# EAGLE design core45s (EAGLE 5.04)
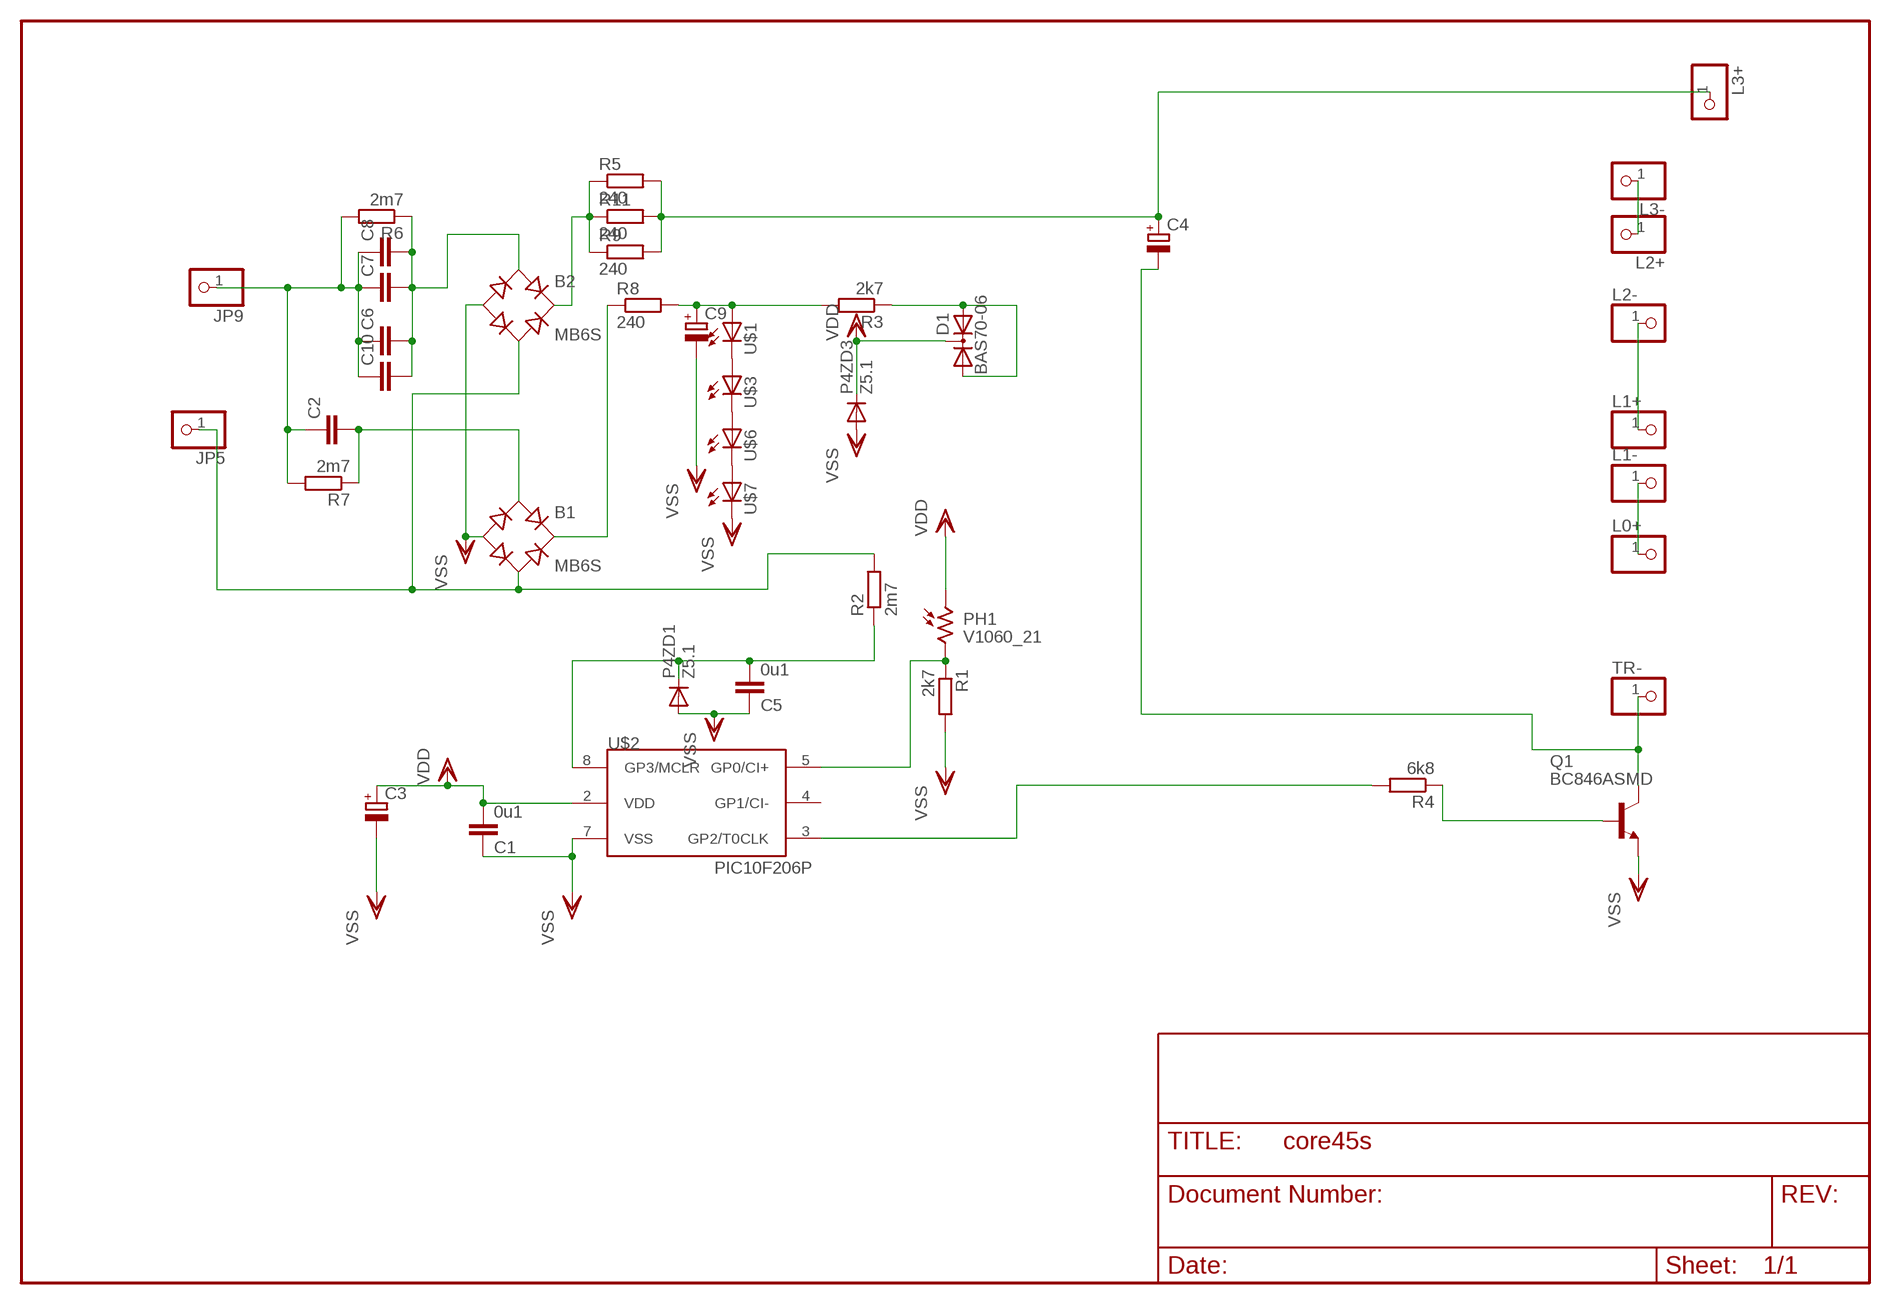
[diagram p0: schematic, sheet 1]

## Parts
B1  MB6S  [SOIC-4]
B2  MB6S  [SOIC-4]
C1  0u1  C-EUC1206  [C1206]
C2  C-EU102-043X133  [C102-043X133]
C3  CPOL-EU5-13  [2,5-5-FLAT]
C4  CPOL-EUTT5D11L  [TT5D11L]
C5  0u1  C-EUC1206  [C1206]
C6  C-EU150-064X183  [C150-064X183]
C7  C-EU150-054X183  [C150-054X183]
C8  C-EU150-054X183  [C150-054X183]
C9  CPOL-EUTT5D11L  [TT5D11L]
C10  C-EU150-064X183  [C150-064X183]
D1  BAS70-06  [SOT23]
JP5  PINHD-1X1  [1X01]
JP9  PINHD-1X1  [1X01]
L0+  PINHD-1X1  [1X01]
L1+  PINHD-1X1  [1X01]
L1-  PINHD-1X1  [1X01]
L2+  PINHD-1X1  [1X01]
L2-  PINHD-1X1  [1X01]
L3+  PINHD-1X1  [1X01]
L3-  PINHD-1X1  [1X01]
P4ZD1  Z5.1  DIODE-MINIMELF  [MINIMELF]
P4ZD3  Z5.1  DIODE-MINIMELF  [MINIMELF]
PH1  V1060_21  [TO-5_V10]
Q1  BC846ASMD  [SOT23]
R1  2k7  R-EU_R0805  [R0805]
R2  2m7  R-EU_R1206  [R1206]
R3  2k7  R-EU_R0805  [R0805]
R4  6k8  R-EU_R0805  [R0805]
R5  240  R-EU_R1206  [R1206]
R6  2m7  R-EU_R1206  [R1206]
R7  2m7  R-EU_R1206  [R1206]
R8  240  R-EU_R1206  [R1206]
R9  240  R-EU_R1206  [R1206]
R11  240  R-EU_R1206  [R1206]
TR-  PINHD-1X1  [1X01]
U$1  LED5MM  [LED5MM]
U$2  PIC10F206P  [DIL8]
U$3  LED5MM  [LED5MM]
U$6  LED5MM  [LED5MM]
U$7  LED5MM  [LED5MM]

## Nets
AC1: B1.~2(AC2) B2.~2(AC2) JP5.1 R2.2
AC2: C2.1 C6.1 C7.1 C8.1 C10.1 JP9.1 R6.2 R7.2
D+: C4.+ L3+.1 R5.2 R9.2 R11.2
LED-: C4.- Q1.3(C) TR-.1
N$1: C5.2 P4ZD1.C R2.1 U$2.8(GP3/MCLR)
N$2: B1.+ R8.1
N$3: L0+.1 L1-.1
N$4: C9.+ R3.2 R8.2 U$1.A
N$5: D1.1(A1) D1.2(A2) R3.1
N$6: L1+.1 L2-.1
N$7: U$1.K(C) U$3.A
N$8: B1.~1(AC1) C2.2 R7.1
N$9: B2.~1(AC1) C6.2 C7.2 C8.2 C10.2 R6.1
N$10: U$3.K(C) U$6.A
N$11: B2.+ R5.1 R9.1 R11.1
N$12: Q1.1(B) R4.1
N$13: L2+.1 L3-.1
N$15: R4.2 U$2.3(GP2/T0CLK)
N$16: U$6.K(C) U$7.A
N$17: PH1.2 R1.1 U$2.5(GP0/CI+)
VDD: C1.2 C3.+ D1.3(C) P4ZD3.C PH1.1 U$2.2(VDD)
VSS: B1.- B2.- C1.1 C3.- C5.1 C9.- P4ZD1.A P4ZD3.A Q1.2(E) R1.2 U$2.7(VSS) U$7.K(C)
Unconnected: U$2.4(GP1/CI-)

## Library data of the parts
B1 B2 = rectifier:MB*S: Bridge Rectifier Source: http://www.fairchildsemi.com/ds/MB/MB6S.pdf
C1 C5 = rcl:C-EU: CAPACITOR, European symbol
C2 C6-C8 C10 = rcl-2:C-EU: CAPACITOR, European symbol
C3 C4 C9 = rcl-2:CPOL-EU: POLARIZED CAPACITOR, European symbol
D1 = diode:BAS70-06: Silicon Schottky Diodes General-purpose diode for high-speed switching
JP5 JP9 L0+ L1+ L1- L2+ L2- L3+ L3- TR- = pinhead(2):PINHD-1X1: PIN HEADER
P4ZD1 P4ZD3 = diode:DIODE-: DIODE
PH1 = photo-elements:?1060*: Sensor Street Light control
Q1 = transistor-npn:BC846*: NPN Transistor
R1-R9 R11 = rcl-2:R-EU_: RESISTOR, European symbol
U$1 U$3 U$6 U$7 = led(3):LED: LED
U$2 = microchip-3:PIC10F2*: uPC nW 0,25/0,5k Program Flash memory Comparator

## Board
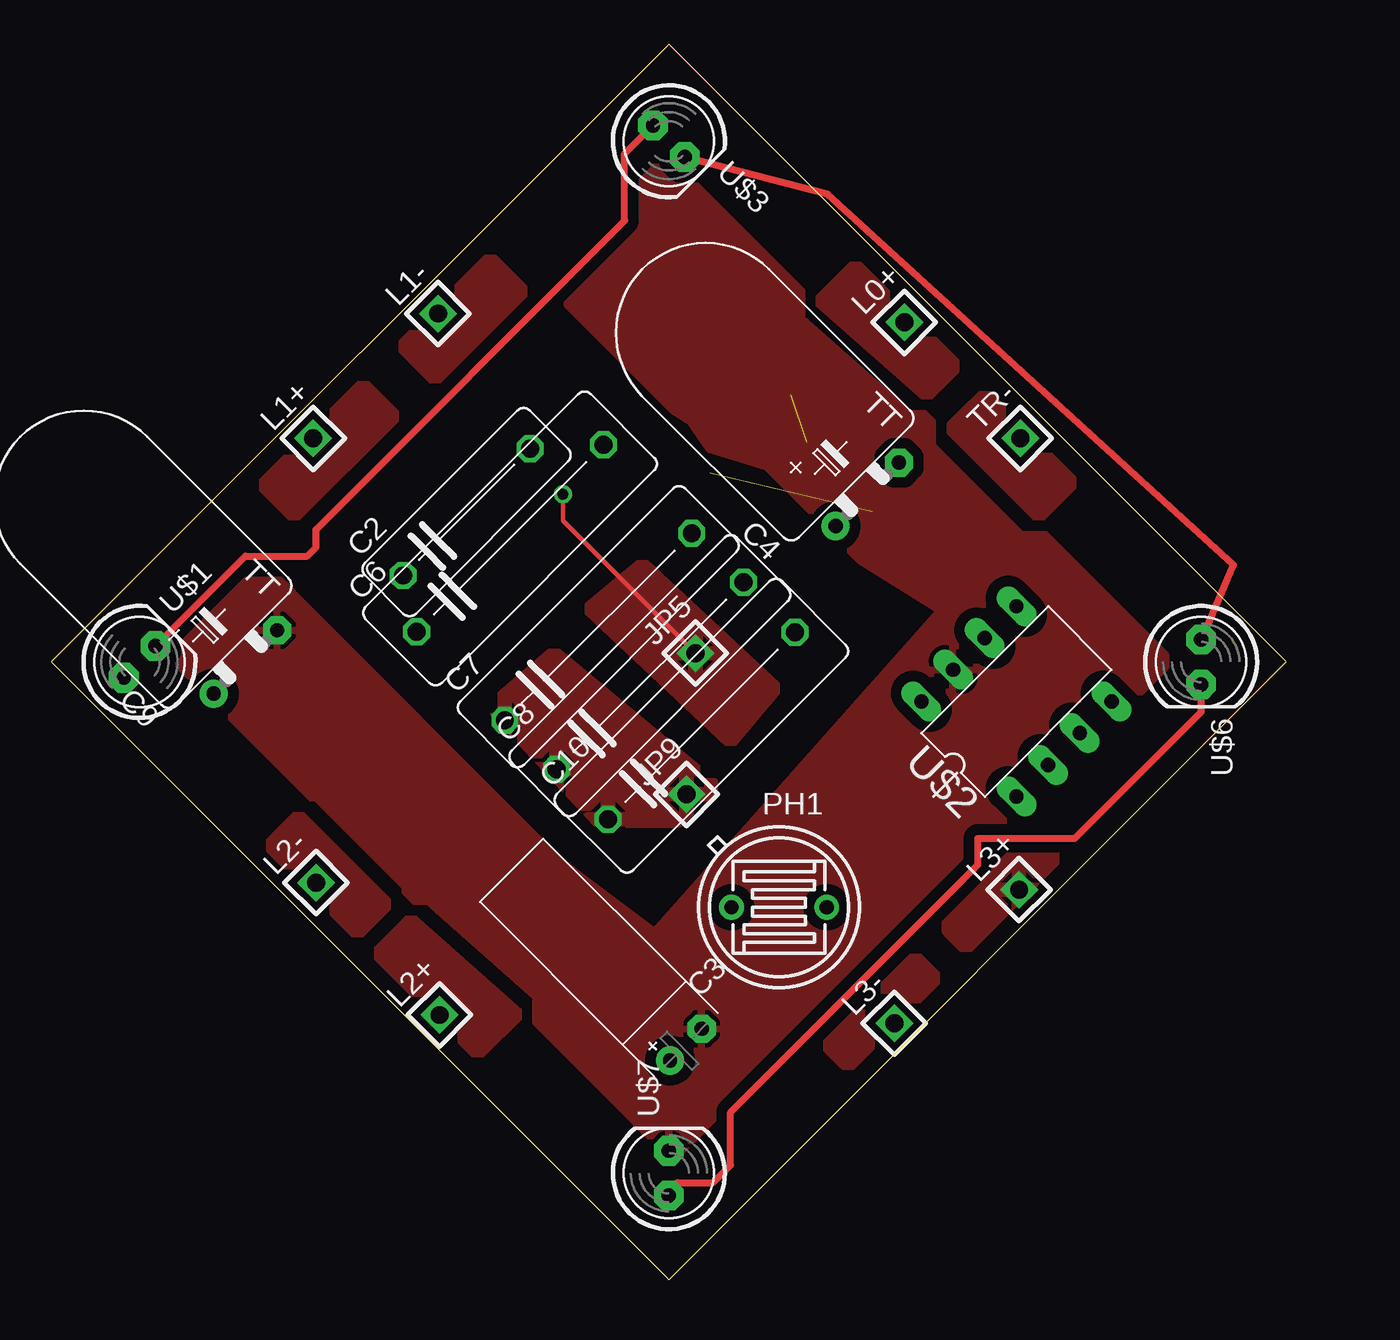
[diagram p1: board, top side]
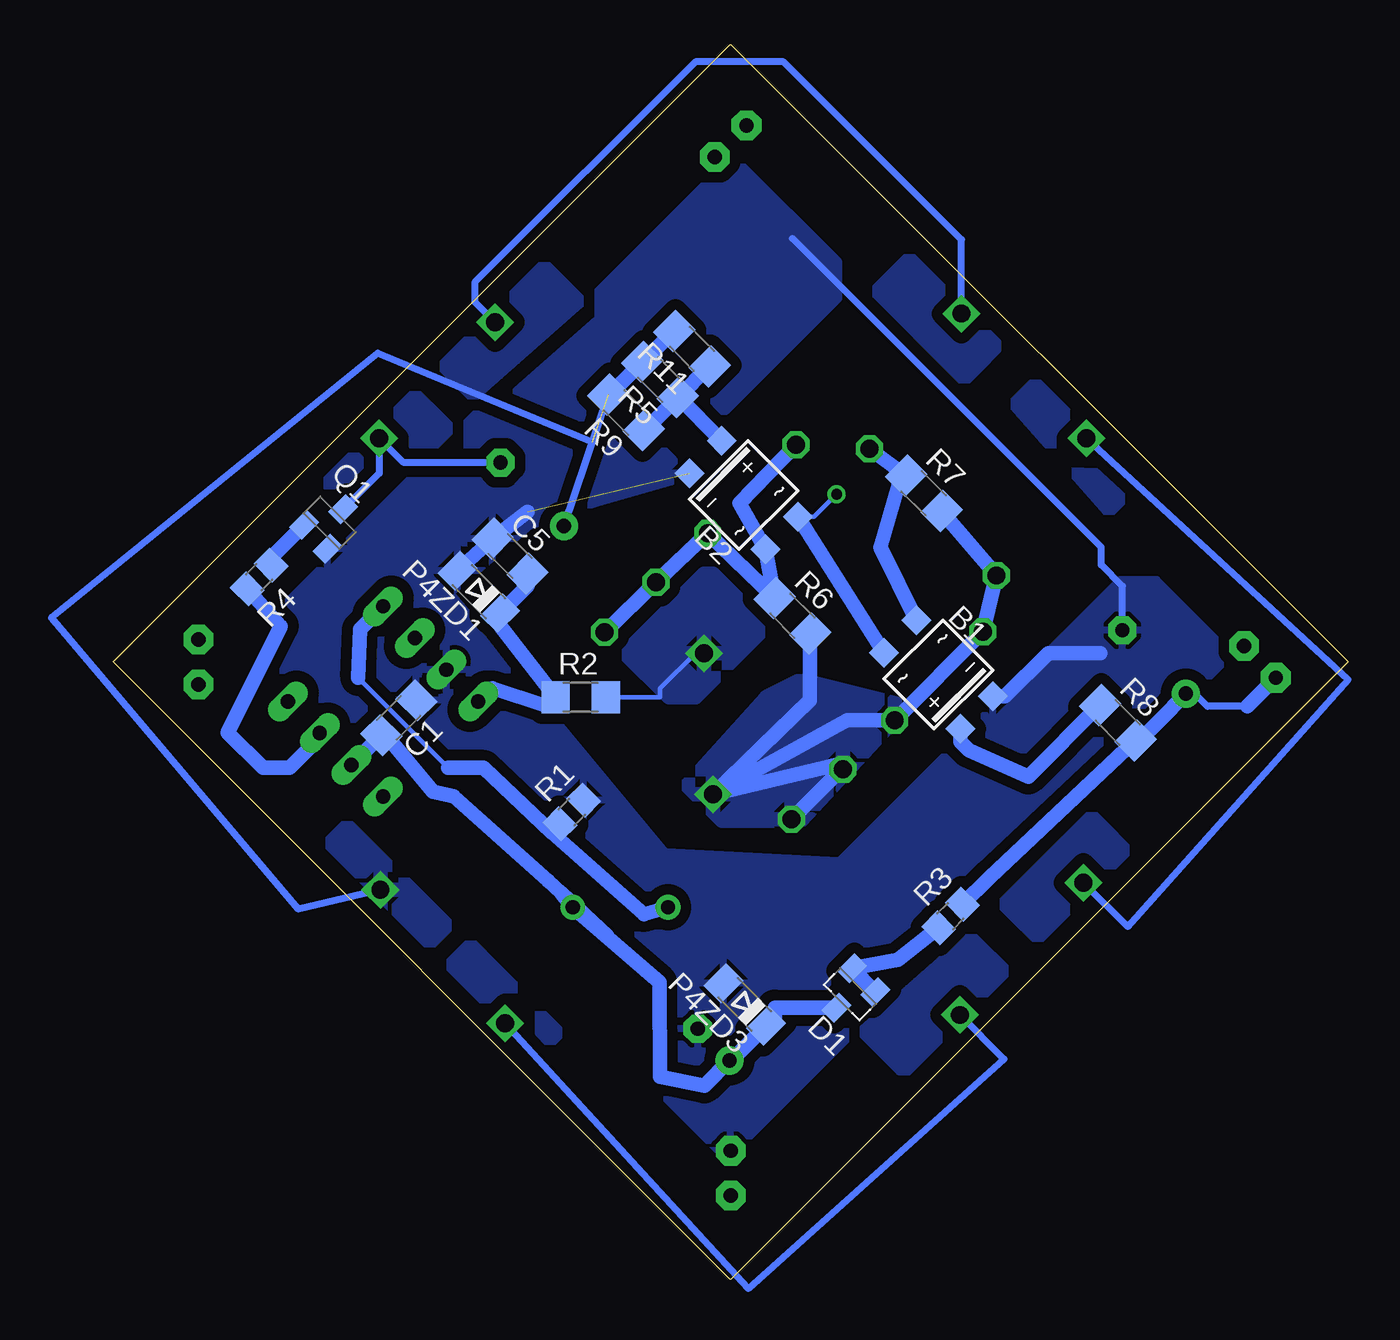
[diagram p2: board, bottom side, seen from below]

Size 70 x 70 mm. Coordinates in mm from the lower left corner, seen from the top.
Outline: 35,0 70,35 35,70 0,35 35,0
Copper layers (1*16): Top 0.035mm / dielectric 1.5mm / Bottom 0.035mm
Design rules "default": minimum track width 10mil, minimum drill 24mil, track to track 8mil, track to pad 8mil, pad to pad 8mil, via to via 8mil, smd to smd 8mil, copper to edge 40mil, drill to drill 8mil, minimum pad ring 10mil, minimum via ring 8mil, stop-mask expansion 4mil, vias tented up to drill 0mil, thermal gap 10mil

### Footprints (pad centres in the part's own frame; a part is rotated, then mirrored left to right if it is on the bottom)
SOIC-4 = smd 1.2 x 1.2: + 1.3,3.05; - -1.3,3.05; ~1 -1.3,-3.05; ~2 1.3,-3.05
C1206 = smd 1.6 x 1.8: 1 -1.4,0; 2 1.4,0
C102-043X133 = drill 1.016 octagon: 1 -5.08,0; 2 5.08,0
2,5-5-FLAT = drill 0.813 pad 1.6 round: + -1.27,0 | drill 0.813 pad 1.6 octagon: - 1.27,0
TT5D11L = drill 0.813 pad 1.6 round: + -2.54,0 | drill 0.813 pad 1.6 octagon: - 2.54,0
C150-064X183 = drill 1.016 octagon: 1 -7.493,0; 2 7.493,0
C150-054X183 = drill 1.016 octagon: 1 -7.493,0; 2 7.493,0
SOT23 = smd 1 x 1.4: 1 -0.95,-1.1; 2 0.95,-1.1; 3 0,1.1
1X01 = drill 1.016 square: 1 0,0
MINIMELF = smd 1.4 x 1.8: A 1.7,0; C -1.7,0
TO-5_V10 = drill 0.8 pad 1.4 round: 1 -2.7,0; 2 2.7,0
R0805 = smd 1.3 x 1.5: 1 -0.95,0; 2 0.95,0
R1206 = smd 1.6 x 1.803: 1 -1.422,0; 2 1.422,0
LED5MM = drill 0.813 pad 1.676 octagon: A -1.27,0; K 1.27,0
DIL8 = drill 0.813 long: 1 -3.81,-3.81; 2 -1.27,-3.81; 3 1.27,-3.81; 4 3.81,-3.81; 5 3.81,3.81; 6 1.27,3.81; 7 -1.27,3.81; 8 -3.81,3.81

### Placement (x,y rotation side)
B1  23.22,34.29 225 bottom
B2  34.27,44.46 45 bottom
C1  53.81,31.84 225 bottom
C2  23.53,43.49 45 top
C3  35.96,13.32 45 top
C4  46.24,44.49 45 top
C5  47.5,41 315 bottom
C6  26,42 45 top
C7  31,37 45 top
C8  33.92,34.22 45 top
C9  11,35 45 top
C10  36.84,31.39 45 top
D1  28.23,16.19 135 bottom
JP5  36.5,35.5 45 top
JP9  36,27.5 45 top
L0+  48.34,54.24 45 top
L1+  14.85,47.67 45 top
L1-  21.92,54.74 45 top
L2+  22,15 45 top
L2-  15,22.5 45 top
L3+  54.85,22.1 45 top
L3-  47.78,14.53 45 top
P4ZD1  49.26,38.97 135 bottom
P4ZD3  34.2,15.59 135 bottom
PH1  41.25,21.11 180 top
Q1  57.73,42.87 315 bottom
R1  44,26.5 45 bottom
R2  43.5,33 0 bottom
R3  22.54,20.6 45 bottom
R4  61.72,39.81 225 bottom
R5  39,51 135 bottom
R6  31.5,37.62 315 bottom
R7  24.06,44.55 315 bottom
R8  13.06,31.56 315 bottom
R9  40.92,49.14 135 bottom
R11  37.2,52.75 135 bottom
TR-  54.91,47.67 45 top
U$1  5,35 45 top
U$2  54.7,32.76 45 top
U$3  35,64.5 315 top
U$6  65.17,35 270 top
U$7  35,6.04 90 top

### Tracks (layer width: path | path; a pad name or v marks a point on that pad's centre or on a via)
AC1  (via drill 0.6)
  Top 0.254: JP5.1 29,43 v29,44.5
  Bottom 0.254: v29,44.5 30.28,43.22 B2.~2 | R2.2 39,33 39,33.5 37,35.5 JP5.1
  Bottom 0.813: B1.~2 B2.~2
  pour Bottom (isolate 0.61): 33,37 37,33 38.5,33 41,35.5 36.5,40 36,40
  pour Top (isolate 0.61): 30.5,38 38.5,30.5 41,33.5 33.5,40.5
AC2
  Bottom 0.813: JP9.1 28.41,31.7 C7.1 C6.1 C2.1 R7.2 | JP9.1 28.89,29.19 C8.1 28.71,28.93 C10.1 | JP9.1 30.49,32.83 R6.2
  pour Bottom (isolate 0.813, rank 2): 25,32.5 31,34 33,33 37.5,28 35.5,26 31,26
  pour Top (isolate 0.813, rank 2): 25,32.5 28.5,35.5 37.5,28 35.5,26 31,26
D+  (1 unrouted)
  Bottom 0.406: C4.+ R9.2 | L3+.1 59.5,21 73.5,37.5 55,52.5 42.84,47.45
  Bottom 0.813: R11.2 39.96,52.01 R5.2 41.86,50.15 R9.2
  pour Bottom (isolate 0.61, rank 2): 49.61,50.14 51.73,52.26 46.07,57.92 45.72,57.57 43.6,55.45
  pour Top (isolate 0.61, rank 2): 49.61,50.14 51.73,52.26 46.07,57.92 45.72,57.57 43.6,55.45
  pour Bottom (isolate 0.61, rank 2): 18.86,49.61 16.74,51.73 11.08,46.07 11.43,45.72 13.55,43.6
  pour Top (isolate 0.61, rank 2): 58.36,23.61 56.24,25.73 50.58,20.07 50.93,19.72 53.05,17.6
  pour Top (isolate 0.61, rank 2): 20.39,20.36 18.27,18.24 23.93,12.58 24.28,12.93 26.4,15.05
  pour Top (isolate 0.61, rank 2): 11.64,45.39 13.76,43.27 19.42,48.93 19.07,49.28 16.95,51.4
  pour Bottom (isolate 0.61, rank 2): 58.86,23.61 56.74,25.73 51.08,20.07 51.43,19.72 53.55,17.6
  pour Bottom (isolate 0.61, rank 2): 21.39,19.36 19.27,17.24 24.93,11.58 25.28,11.93 27.4,14.05
D-
  pour Bottom (isolate 0.61): 58.45,45.75 55.97,43.28 51.02,48.23 53.5,50.7
  pour Top (isolate 0.61): 58.45,45.75 55.97,43.28 51.02,48.23 53.5,50.7
  pour Top (isolate 0.61): 48.75,18.45 51.22,15.97 46.27,11.02 43.8,13.5
  pour Top (isolate 0.61): 11.55,23.75 14.03,26.22 18.98,21.27 16.5,18.8
  pour Top (isolate 0.61): 21.75,51.05 19.28,53.53 24.23,58.48 26.7,56
  pour Bottom (isolate 0.61): 49.75,18.95 52.22,16.47 47.27,11.52 44.8,14
  pour Bottom (isolate 0.61): 12.05,23.75 14.53,26.22 19.48,21.27 17,18.8
  pour Bottom (isolate 0.61): 21.75,51.05 19.28,53.53 24.23,58.48 26.7,56
LED-
  Bottom 0.406: C4.- 53.53,46.29 TR-.1 54.91,45.69 Q1.3
N$1
  Bottom 0.813: U$2.8 49.24,32.76 48.5,33.5 45.5,32.51 R2.1 48.06,37.06 P4ZD1.C 46.51,39.32 C5.2
N$2
  Bottom 0.813: R8.1 18.13,28.5 21.5,30 21.99,30.49 B1.+
N$3
  Bottom 0.406: L1-.1 21.92,58.92 32,69 37,69 49.5,56.5 49.5,55.4 L0+.1
N$4
  Bottom 0.406: 5.72,32.48 7.99,32.48 8.5,33 9,33 C9.+
  Bottom 0.813: U$1.A 5.72,32.48 | C9.+ 12.29,30.06 R8.2 20.34,22.77 R3.2
N$5
  Bottom 0.813: R3.1 25.5,18.14 D1.2 D1.1
N$6
  Bottom 0.406: L1+.1 0,34 12.5,20 L2-.1
N$7
  Top 0.406: U$1.K 11,41 14.5,41 15,41.5 15,42.5 32.5,60 32.5,63.8 U$3.A
N$8
  Bottom 0.813: C2.2 R7.1 25.5,45 26.5,41.5 B1.~1
N$9
  Bottom 0.813: C6.2 34.5,44 B2.~1 R6.1 C7.2 C8.2 C10.2
N$10
  Top 0.406: U$6.A 67,40.5 44,61.5 U$3.K
N$11
  Bottom 0.813: B2.+ 37.97,49.99 | 37.97,49.99 R5.1 39.85,48.14 R9.1 | 37.97,49.99 36.22,51.74 R11.1
N$12
  Bottom 0.813: Q1.1 61.05,40.89 R4.1
N$13
  Bottom 0.406: L2+.1 19.5,12.5 34,-0.5 L3-.1
N$15
  Bottom 0.813: U$2.3 58.29,30.71 60,29 61.5,29 63.5,31 60.5,37.03 R4.2
N$16
  Top 0.406: U$6.K 65.17,32.17 58,25 52.5,25 52.5,23.5 38.5,9.5 38.5,6.5 37.5,5.5 35.5,5.5 34.5,4.5 34.73,4.5 U$7.A
N$17
  Bottom 0.254: 51,29 56.1,34.1
  Bottom 0.813: U$2.5 56,36.85 56.1,34.1 | 45.13,25.34 39.91,20.71 PH1.2 | 45.13,25.34 49,29 51,29 | 45.13,25.34 R1.1
VDD
  Bottom 0.813: D1.3 32.5,15.42 32.5,14.5 32.61,14.39 P4ZD3.C 34.96,12.42 C3.+ 36.49,11 39,11.5 39.04,16.84 PH1.1 44.61,21.92 | 44.61,21.92 42,19.5 | 44.61,21.92 45.35,22.6 50.7,27.4 51.85,27.65 54.3,30.55 C1.2 U$2.2
VSS  (1 unrouted)
  Bottom 0.406: C9.- 12.8,39.3 14,40.5 14,41.5 31.5,59
  Bottom 0.813: 14.04,35.5 17,35.5 19.45,33.05 B1.- | 46.5,43.5 C5.1 P4ZD1.A
  pour Bottom (isolate 0.61, rank 5): 6.59,35.41 10.84,39.66 12.96,39.66 28.87,23.75 38.7,24.25 50.84,38.89 46.34,42.72 42.54,44.02 37.29,45.52 39.73,48.08 35.23,49.2 28.87,55.57 28.87,57.69 34.53,63.34 35.23,63.34 63.16,35.41 63.16,34.71 35.59,7.13 34.88,7.13
  pour Top (isolate 0.61, rank 5): 6.59,35.41 10.84,39.66 12.96,39.66 28.87,23.75 34.2,19.75 50.34,37.89 45.84,40.72 40.54,46.02 37.29,47.02 36.23,48.58 35.23,49.2 28.87,55.57 28.87,57.69 34.53,63.34 35.23,63.34 63.16,35.41 63.16,34.71 35.59,7.13 34.88,7.13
